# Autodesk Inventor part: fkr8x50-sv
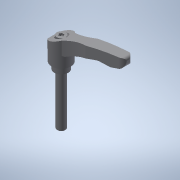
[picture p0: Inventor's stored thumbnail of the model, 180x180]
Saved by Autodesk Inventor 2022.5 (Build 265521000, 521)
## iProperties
Created: 2017-09
Part Number: fkr8x50-sv
Material: 一般
Document SubType Name: Modeling
Designer: imaocorp
Density: 1 g/cm^3
Appearance: 既定
Author: imaocorp
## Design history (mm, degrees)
node "fkr8x50-sv.x_t1"
node "fkr8x50-sv"
node "Base1"
